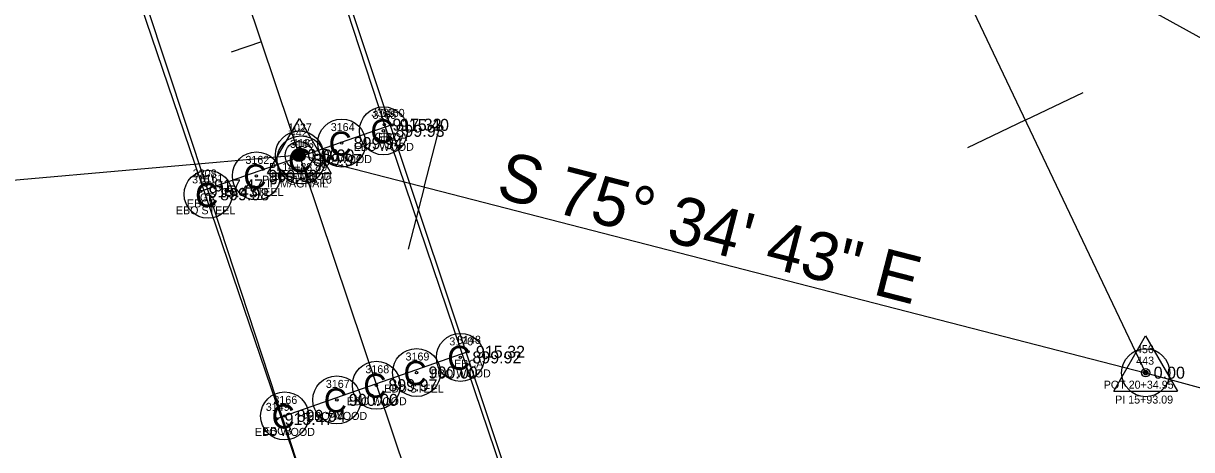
# Model space of a CAD drawing. Extents: x 1528109 to 1531398, y 1157799 to 1162548.
# Drawn here: x 1529613.7 to 1529759.7, y 1160240.8 to 1160294.1 of the extents above; entities that cross this region are included whole.
import ezdxf

# ---------------------------------------------------------------- set-up
doc = ezdxf.new("R2010")
doc.units = 0
for name, color, linetype in [('RD_EX_Bridge', 7, 'Continuous'), ('RD_EX_Bridge_txCode', 7, 'Continuous'), ('RD_EX_DV_Prop_txCode', 7, 'Continuous'), ('RD_EX_DV_PropPin', 7, 'Continuous'), ('RD_EX_GuardRail', 7, 'Continuous'), ('RD_EX_GuardRail_txCode', 7, 'Continuous'), ('RD_EX_H2O', 7, 'Continuous'), ('RD_EX_TX_Bridge_ELEV', 7, 'Continuous'), ('RD_EX_TX_DV_Prop_ELEV', 7, 'Continuous'), ('RD_EX_TX_GuardRail_ELEV', 7, 'Continuous'), ('RD_HC_Cl', 7, 'Continuous'), ('RD_HC_Data', 7, 'Continuous'), ('RD_HC_Data_Tic', 7, 'Continuous'), ('RD_HC_Survey_ELEV', 7, 'Continuous'), ('RD_HC_txCode', 7, 'Continuous'), ('RD_SMD_Locator', 7, 'Continuous')]:
    doc.layers.add(name, color=color, linetype=linetype)

msp = doc.modelspace()

# ---------------------------------------------------------------- linework, layer by layer
at = {"layer": 'RD_EX_Bridge'}
for p, q in [((1529659.72, 1160281.4), (1529635.82, 1160273.09)), ((1529669.22, 1160253.05), (1529645.31, 1160244.67))]:
    msp.add_line(p, q, dxfattribs=at)
msp.add_lwpolyline([(1529640.55, 1160338.19), (1529616.81, 1160330.27), (1529655.43, 1160216.77), (1529678.49, 1160224.61), (1529640.55, 1160338.19)], dxfattribs=at)
for centre in [(1529658.67, 1160280.66), (1529653.45, 1160279.13), (1529648.37, 1160277.03), (1529642.79, 1160275.03), (1529636.76, 1160272.73), (1529668.28, 1160252.35), (1529662.8, 1160250.46), (1529657.78, 1160248.87), (1529652.84, 1160247.04), (1529646.32, 1160245.04)]:
    msp.add_circle(centre, 3, dxfattribs=at)
at = {"layer": 'RD_EX_DV_PropPin'}
for p, q in [((1529647.39, 1160277.38), (1529647.39, 1160277.78)), ((1529647.43, 1160277.28), (1529647.43, 1160277.88)), ((1529647.46, 1160277.21), (1529647.46, 1160277.95)), ((1529647.5, 1160277.15), (1529647.5, 1160278.01)), ((1529647.53, 1160277.1), (1529647.53, 1160278.05)), ((1529647.57, 1160277.06), (1529647.57, 1160278.09)), ((1529647.6, 1160277.03), (1529647.6, 1160278.13)), ((1529647.64, 1160277), (1529647.64, 1160278.16)), ((1529647.67, 1160276.97), (1529647.67, 1160278.19)), ((1529647.71, 1160276.94), (1529647.71, 1160278.21)), ((1529647.74, 1160276.92), (1529647.74, 1160278.24)), ((1529647.78, 1160276.9), (1529647.78, 1160278.25)), ((1529647.81, 1160276.89), (1529647.81, 1160278.27)), ((1529647.85, 1160276.87), (1529647.85, 1160278.29)), ((1529647.88, 1160276.86), (1529647.88, 1160278.3)), ((1529647.92, 1160276.85), (1529647.92, 1160278.31)), ((1529647.95, 1160276.84), (1529647.95, 1160278.32)), ((1529647.99, 1160276.83), (1529647.99, 1160278.33)), ((1529648.02, 1160276.83), (1529648.02, 1160278.33)), ((1529648.06, 1160276.82), (1529648.06, 1160278.34)), ((1529648.09, 1160276.82), (1529648.09, 1160278.34)), ((1529648.13, 1160276.82), (1529648.13, 1160278.34)), ((1529648.16, 1160276.82), (1529648.16, 1160278.34)), ((1529648.2, 1160276.82), (1529648.2, 1160278.34)), ((1529648.23, 1160276.83), (1529648.23, 1160278.33)), ((1529648.27, 1160276.83), (1529648.27, 1160278.33)), ((1529648.3, 1160276.84), (1529648.3, 1160278.32)), ((1529648.34, 1160276.85), (1529648.34, 1160278.31)), ((1529648.37, 1160276.86), (1529648.37, 1160278.3)), ((1529648.41, 1160276.87), (1529648.41, 1160278.29)), ((1529648.44, 1160276.89), (1529648.44, 1160278.27)), ((1529648.48, 1160276.9), (1529648.48, 1160278.25)), ((1529648.51, 1160276.92), (1529648.51, 1160278.24)), ((1529648.55, 1160276.94), (1529648.55, 1160278.21)), ((1529648.58, 1160276.97), (1529648.58, 1160278.19)), ((1529648.62, 1160277), (1529648.62, 1160278.16)), ((1529648.65, 1160277.03), (1529648.65, 1160278.13)), ((1529648.69, 1160277.06), (1529648.69, 1160278.09)), ((1529648.72, 1160277.1), (1529648.72, 1160278.05)), ((1529648.76, 1160277.15), (1529648.76, 1160278.01)), ((1529648.79, 1160277.21), (1529648.79, 1160277.95)), ((1529648.83, 1160277.28), (1529648.83, 1160277.88)), ((1529648.86, 1160277.38), (1529648.86, 1160277.78))]:
    msp.add_line(p, q, dxfattribs=at)
for radius in [1.75, 0.761]:
    msp.add_circle((1529648.13, 1160277.58), radius, dxfattribs=at)
at = {"layer": 'RD_EX_GuardRail'}
for points in [[(1529639.21, 1160341.22), (1529658.79, 1160281.43), (1529679.51, 1160220.29)], [(1529616.58, 1160333.92), (1529636.5, 1160273.84), (1529656.54, 1160212.79)]]:
    msp.add_lwpolyline(points, dxfattribs=at)
at = {"layer": 'RD_EX_H2O'}
msp.add_lwpolyline([(1529726.41, 1160311.29), (1529822.85, 1160258.09), (1529888.47, 1160243.37), (1529986.9, 1160229.42), (1530037.08, 1160228.61), (1530104.23, 1160168.21), (1530147.93, 1160110.54), (1530175.68, 1160088.08)], dxfattribs=at)
at = {"layer": 'RD_HC_Cl'}
for p, q in [((1529913.5, 1159487.74), (1529527.85, 1160635.77)), ((1529658.39, 1160450.88), (1529753.92, 1160250.44)), ((1529525.22, 1160266.9), (1529648.16, 1160277.64)), ((1529648.16, 1160277.64), (1529753.92, 1160250.44)), ((1529753.92, 1160250.44), (1530030.68, 1160174.79))]:
    msp.add_line(p, q, dxfattribs=at)
at = {"layer": 'RD_HC_Data'}
for p, q in [((1529644.19, 1160275.34), (1529648.16, 1160282.22)), ((1529648.16, 1160282.22), (1529652.13, 1160275.34)), ((1529644.19, 1160275.34), (1529652.13, 1160275.34)), ((1529749.95, 1160248.15), (1529753.92, 1160255.03)), ((1529753.92, 1160255.03), (1529757.89, 1160248.15)), ((1529749.95, 1160248.15), (1529757.89, 1160248.15))]:
    msp.add_line(p, q, dxfattribs=at)
for centre, radius in [((1529648.16, 1160277.64), 3), ((1529648.16, 1160277.64), 0.529), ((1529648.16, 1160277.64), 0.282), ((1529753.92, 1160250.44), 3), ((1529753.92, 1160250.44), 0.529), ((1529753.92, 1160250.44), 0.282)]:
    msp.add_circle(centre, radius, dxfattribs=at)
at = {"layer": 'RD_HC_Data_Tic'}
for p, q in [((1529643.41, 1160291.76), (1529639.62, 1160290.49)), ((1529738.88, 1160281.99), (1529746.1, 1160285.43)), ((1529738.88, 1160281.99), (1529731.66, 1160278.55)), ((1529663.76, 1160273.62), (1529665.76, 1160281.37)), ((1529663.76, 1160273.62), (1529661.77, 1160265.88))]:
    msp.add_line(p, q, dxfattribs=at)
at = {"layer": 'RD_SMD_Locator'}
for centre in [(1529658.79, 1160281.43), (1529659.72, 1160281.4), (1529658.67, 1160280.66), (1529653.45, 1160279.13), (1529648.13, 1160277.58), (1529648.16, 1160277.64), (1529648.16, 1160277.64), (1529648.37, 1160277.03), (1529642.79, 1160275.03), (1529635.82, 1160273.09), (1529636.5, 1160273.84), (1529636.76, 1160272.73), (1529668.28, 1160252.35), (1529669.22, 1160253.05), (1529662.8, 1160250.46), (1529753.92, 1160250.44), (1529753.92, 1160250.44), (1529657.78, 1160248.87), (1529652.84, 1160247.04), (1529646.32, 1160245.04), (1529645.31, 1160244.67)]:
    msp.add_circle(centre, 0.15, dxfattribs=at)

# ---------------------------------------------------------------- texts
at = {"layer": 'RD_EX_Bridge'}
for p in [(1529657.04, 1160279.1), (1529651.82, 1160277.57), (1529646.74, 1160275.47), (1529641.16, 1160273.47), (1529635.13, 1160271.16), (1529666.65, 1160250.79), (1529661.17, 1160248.9), (1529656.15, 1160247.31), (1529651.21, 1160245.48), (1529644.69, 1160243.48)]:
    msp.add_text('C', height=3, dxfattribs=at).set_placement(p)
at = {"layer": 'RD_EX_Bridge_txCode'}
for s, p in [('3165', (1529657.3, 1160282.16)), ('3150', (1529658.34, 1160282.4)), ('3164', (1529652.08, 1160280.63)), ('EBCA', (1529658.01, 1160279.4)), ('3163', (1529647, 1160278.53)), ('EBO WOOD', (1529654.96, 1160278.16)), ('3162', (1529641.42, 1160276.53)), ('EBO WOOD', (1529649.73, 1160276.63)), ('EBO WOOD', (1529644.65, 1160274.53)), ('3151', (1529634.75, 1160274.09)), ('3161', (1529635.68, 1160274.23)), ('EBO STEEL', (1529638.75, 1160272.53)), ('EBO STEEL', (1529632.72, 1160270.23)), ('EBCB', (1529634.11, 1160271.09)), ('3170', (1529666.9, 1160253.85)), ('3148', (1529667.87, 1160254.05)), ('3169', (1529661.43, 1160251.96)), ('3168', (1529656.41, 1160250.37)), ('EBO WOOD', (1529664.57, 1160249.85)), ('EBCA', (1529667.5, 1160251.05)), ('3167', (1529651.47, 1160248.54)), ('EBO STEEL', (1529658.76, 1160247.96)), ('3149', (1529643.96, 1160245.67)), ('3166', (1529644.92, 1160246.54)), ('EBO WOOD', (1529654.07, 1160246.37)), ('EBO WOOD', (1529649.13, 1160244.54)), ('EBO WOOD', (1529642.6, 1160242.54)), ('EBCB', (1529643.6, 1160242.67))]:
    msp.add_text(s, height=1, dxfattribs=at).set_placement(p)
at = {"layer": 'RD_EX_DV_Prop_txCode'}
for s, p in [('1027', (1529646.74, 1160280.58)), ('IP MAGNAIL', (1529644.11, 1160273.58))]:
    msp.add_text(s, height=1, dxfattribs=at).set_placement(p)
at = {"layer": 'RD_EX_GuardRail_txCode'}
for s, p in [('3309', (1529657.12, 1160282.43)), ('GR2', (1529657.56, 1160279.43)), ('3308', (1529634.84, 1160274.84)), ('GR', (1529635.73, 1160271.84))]:
    msp.add_text(s, height=1, dxfattribs=at).set_placement(p)
at = {"layer": 'RD_EX_TX_Bridge_ELEV'}
for s, p in [('899.93', (1529660.17, 1160279.91)), ('915.40', (1529660.72, 1160280.65)), ('899.94', (1529654.95, 1160278.38)), ('899.97', (1529649.87, 1160276.28)), ('900.00', (1529644.29, 1160274.28)), ('915.43', (1529636.82, 1160272.34)), ('899.98', (1529638.26, 1160271.98)), ('915.32', (1529670.22, 1160252.3)), ('899.92', (1529669.78, 1160251.6)), ('900.00', (1529664.3, 1160249.71)), ('899.97', (1529659.28, 1160248.12)), ('900.00', (1529654.34, 1160246.29)), ('915.47', (1529646.31, 1160243.92)), ('899.94', (1529647.82, 1160244.29))]:
    msp.add_text(s, height=1.5, dxfattribs=at).set_placement(p)
at = {"layer": 'RD_EX_TX_DV_Prop_ELEV'}
msp.add_text('0.00', height=1.5, dxfattribs=at).set_placement((1529651.13, 1160276.83))
at = {"layer": 'RD_EX_TX_GuardRail_ELEV'}
for s, p in [('917.32', (1529659.79, 1160280.68)), ('917.47', (1529637.5, 1160273.09))]:
    msp.add_text(s, height=1.5, dxfattribs=at).set_placement(p)
at = {"layer": 'RD_HC_Data'}
msp.add_text('S 75%%d 34\' 43" E', height=6, rotation=345.5786, dxfattribs=at).set_placement((1529672.57, 1160272.39))
at = {"layer": 'RD_HC_Survey_ELEV'}
for p in [(1529649.16, 1160276.89), (1529649.16, 1160276.89), (1529754.92, 1160249.69), (1529754.92, 1160249.69)]:
    msp.add_text('0.00', height=1.5, dxfattribs=at).set_placement(p)
at = {"layer": 'RD_HC_txCode'}
for s, p in [('442', (1529646.97, 1160279.95)), ('418', (1529647.26, 1160278.64)), ('PI 14+83.89', (1529644.38, 1160275.64)), ('POT 31+85.10', (1529643.49, 1160274.06)), ('456', (1529752.71, 1160252.88)), ('443', (1529752.74, 1160251.44)), ('POT 20+34.95', (1529748.68, 1160248.44)), ('PI 15+93.09', (1529750.1, 1160246.58))]:
    msp.add_text(s, height=1, dxfattribs=at).set_placement(p)

doc.saveas('drawing.dxf')
